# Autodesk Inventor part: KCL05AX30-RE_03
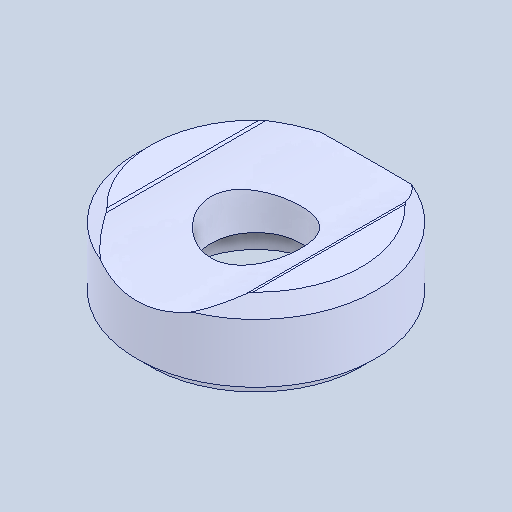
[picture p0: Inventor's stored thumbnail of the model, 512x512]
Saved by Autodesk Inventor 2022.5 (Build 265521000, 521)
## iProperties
Created: 2024-08
Part Number: KCL05AX30-RE_03
Material: 一般
Document SubType Name: Modeling
Designer: ImaoCorp
Density: 1 g/cm^3
Appearance: 既定
Author: ImaoCorp
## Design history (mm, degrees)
feature "KCL05AX30-RE_03"
node "ソリッド1"
